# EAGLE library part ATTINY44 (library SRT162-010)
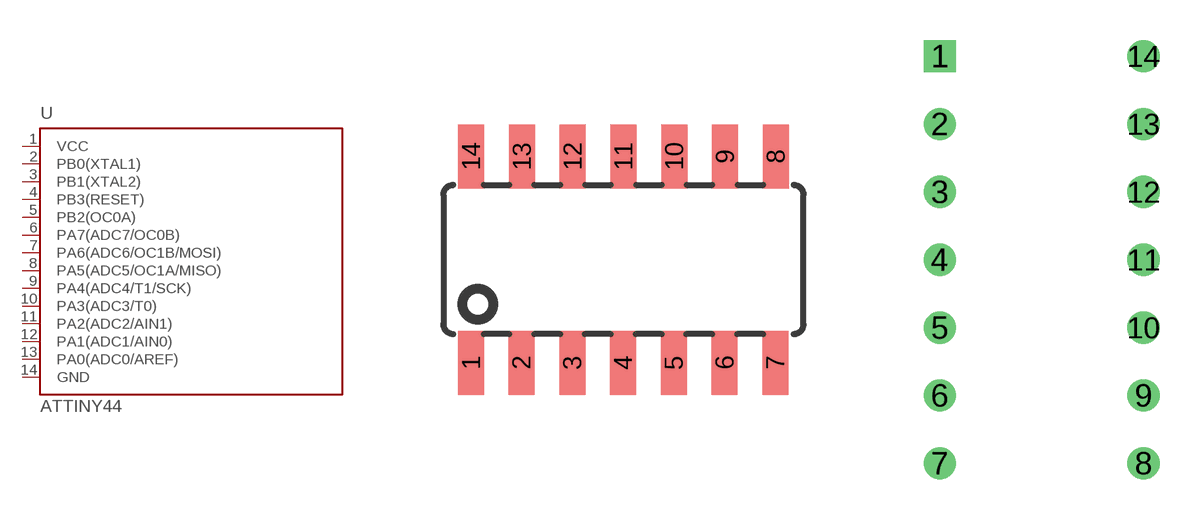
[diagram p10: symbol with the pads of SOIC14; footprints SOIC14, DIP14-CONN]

Designator prefix U

## ATTINY44SOIC  [SOIC14]
1  VCC  pwr
2  PB0(XTAL1)
3  PB1(XTAL2)
4  PB3(RESET)
5  PB2(OC0A)
6  PA7(ADC7/OC0B)
7  PA6(ADC6/OC1B/MOSI)
8  PA5(ADC5/OC1A/MISO)
9  PA4(ADC4/T1/SCK)
10  PA3(ADC3/T0)
11  PA2(ADC2/AIN1)
12  PA1(ADC1/AIN0)
13  PA0(ADC0/AREF)
14  GND  pwr

## ATTINY44DIP  [DIP14-CONN]
Pads as for SOIC14

## Footprint SOIC14 (pad centres in mm)
smd 0.65 x 1.6: 1 -5.715,-2.583; 2 -4.455,-2.583; 3 -3.185,-2.583; 4 -1.915,-2.583; 5 -0.645,-2.583; 6 0.625,-2.583; 7 1.895,-2.583; 8 1.905,2.583; 9 0.635,2.583; 10 -0.635,2.583; 11 -1.905,2.583; 12 -3.175,2.583; 13 -4.445,2.583; 14 -5.715,2.583

## Footprint DIP14-CONN (pad centres in mm)
drill 0.7 square: 1 -3.81,7.62
drill 0.7 round: 2 -3.81,5.08; 3 -3.81,2.54; 4 -3.81,0; 5 -3.81,-2.54; 6 -3.81,-5.08; 7 -3.81,-7.62; 8 3.81,-7.62; 9 3.81,-5.08; 10 3.81,-2.54; 11 3.81,0; 12 3.81,2.54; 13 3.81,5.08; 14 3.81,7.62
